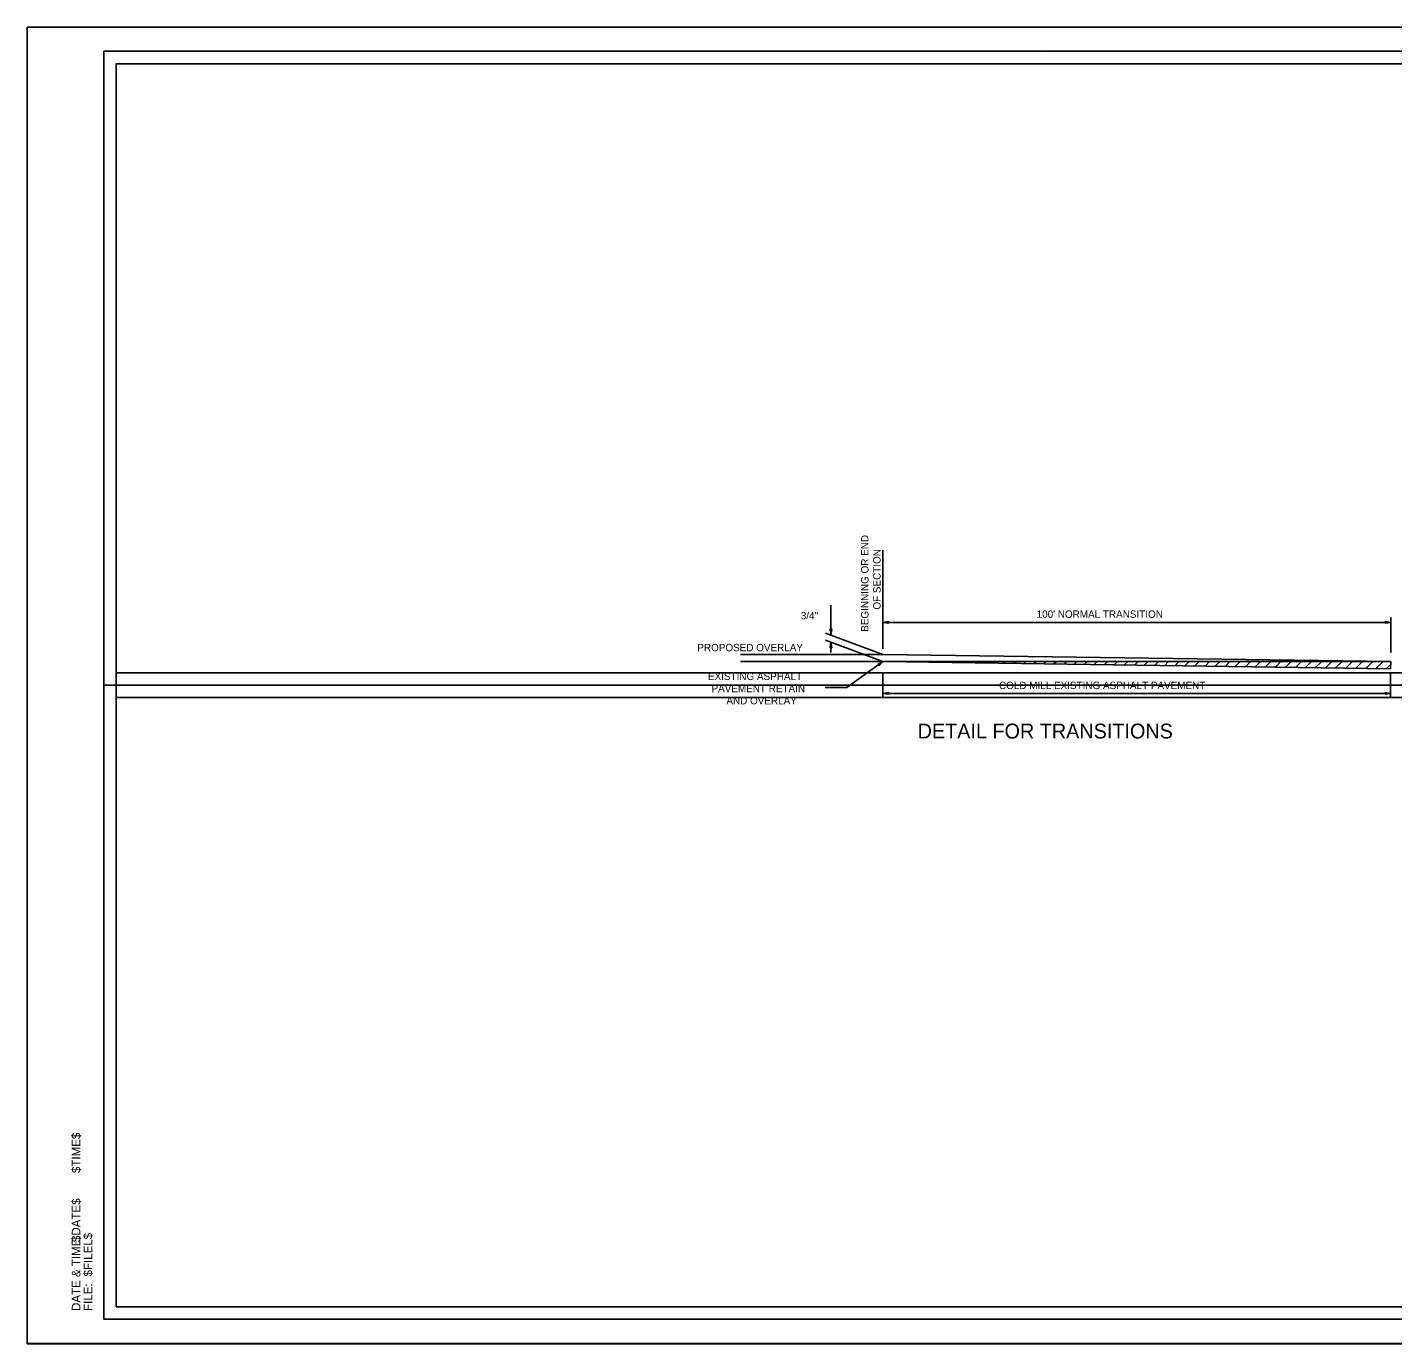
# Model space of a CAD drawing. Extents: x 1372039 to 1372773, y 376713 to 376926.
# Drawn here: x 1372039.3 to 1372260.6, y 376712.7 to 376926 of the extents above; entities that cross this region are included whole.
import ezdxf

# ---------------------------------------------------------------- set-up
doc = ezdxf.new("R2010")
doc.units = 0
for name, color, linetype in [('Default', 7, 'Continuous'), ('R_Border', 7, 'Continuous'), ('R_Border Plan-Plan', 7, 'Continuous'), ('R_No Plot', 7, 'Continuous')]:
    doc.layers.add(name, color=color, linetype=linetype)

msp = doc.modelspace()

# ---------------------------------------------------------------- linework, layer by layer
at = {"layer": 'Default'}
for p, q in [((1372177.98, 376825.29), (1372177.98, 376841.27)), ((1372169.54, 376827.56), (1372169.54, 376832.36)), ((1372260.29, 376824.67), (1372260.29, 376830.36)), ((1372169.41, 376828.45), (1372169.54, 376827.56)), ((1372169.41, 376828.45), (1372169.54, 376827.69)), ((1372169.68, 376828.45), (1372169.41, 376828.45)), ((1372169.46, 376828.45), (1372169.54, 376827.87)), ((1372169.46, 376828.45), (1372169.54, 376828)), ((1372169.5, 376828.45), (1372169.54, 376828.18)), ((1372169.5, 376828.45), (1372169.54, 376828.32)), ((1372169.68, 376828.45), (1372169.54, 376827.56)), ((1372169.59, 376828.45), (1372169.54, 376828.18)), ((1372169.63, 376828.45), (1372169.54, 376827.87)), ((1372169.63, 376828.45), (1372169.54, 376827.69)), ((1372169.59, 376828.45), (1372169.54, 376828)), ((1372169.54, 376828.45), (1372169.54, 376828.32)), ((1372178.92, 376829.69), (1372177.98, 376829.56)), ((1372177.98, 376829.56), (1372260.29, 376829.56)), ((1372178.92, 376829.43), (1372177.98, 376829.56)), ((1372178.92, 376829.65), (1372178.12, 376829.56)), ((1372178.92, 376829.43), (1372178.12, 376829.56)), ((1372178.92, 376829.65), (1372178.3, 376829.56)), ((1372178.92, 376829.47), (1372178.3, 376829.56)), ((1372178.92, 376829.6), (1372178.47, 376829.56)), ((1372178.92, 376829.47), (1372178.47, 376829.56)), ((1372178.92, 376829.6), (1372178.61, 376829.56)), ((1372178.92, 376829.52), (1372178.61, 376829.56)), ((1372178.92, 376829.56), (1372178.78, 376829.56)), ((1372178.92, 376829.52), (1372178.78, 376829.56)), ((1372178.92, 376829.43), (1372178.92, 376829.69)), ((1372259.36, 376829.69), (1372260.29, 376829.56)), ((1372259.36, 376829.69), (1372259.36, 376829.43)), ((1372259.36, 376829.65), (1372259.98, 376829.56)), ((1372259.36, 376829.65), (1372260.11, 376829.56)), ((1372259.36, 376829.6), (1372259.67, 376829.56)), ((1372259.36, 376829.6), (1372259.81, 376829.56)), ((1372259.36, 376829.43), (1372260.29, 376829.56)), ((1372259.36, 376829.52), (1372259.67, 376829.56)), ((1372259.36, 376829.47), (1372259.98, 376829.56)), ((1372259.36, 376829.43), (1372260.11, 376829.56)), ((1372259.36, 376829.47), (1372259.81, 376829.56)), ((1372259.36, 376829.52), (1372259.49, 376829.56)), ((1372259.36, 376829.56), (1372259.49, 376829.56)), ((1372177.98, 376824.36), (1372168.7, 376827.83)), ((1372177.98, 376823.21), (1372168.7, 376826.67)), ((1372169.41, 376825.43), (1372169.54, 376826.36)), ((1372169.41, 376825.43), (1372169.54, 376826.23)), ((1372169.46, 376825.43), (1372169.54, 376826.05)), ((1372169.46, 376825.43), (1372169.54, 376825.92)), ((1372169.68, 376825.43), (1372169.54, 376826.36)), ((1372169.54, 376824.67), (1372169.54, 376826.36)), ((1372169.63, 376825.43), (1372169.54, 376826.23)), ((1372169.63, 376825.43), (1372169.54, 376826.05)), ((1372169.59, 376825.43), (1372169.54, 376825.92)), ((1372154.89, 376824.36), (1372177.98, 376824.36)), ((1372169.41, 376825.43), (1372169.68, 376825.43)), ((1372169.5, 376825.43), (1372169.54, 376825.74)), ((1372169.5, 376825.43), (1372169.54, 376825.56)), ((1372169.59, 376825.43), (1372169.54, 376825.74)), ((1372169.54, 376825.43), (1372169.54, 376825.56)), ((1372260.29, 376823.21), (1372177.98, 376824.36)), ((1372154.89, 376823.21), (1372260.3, 376823.21)), ((1372172.12, 376818.99), (1372177.98, 376823.21)), ((1372177.14, 376822.76), (1372177.98, 376823.21)), ((1372177.14, 376822.76), (1372177.32, 376822.54)), ((1372177.19, 376822.76), (1372177.85, 376823.12)), ((1372177.19, 376822.76), (1372177.72, 376823.03)), ((1372177.19, 376822.72), (1372177.58, 376822.94)), ((1372177.19, 376822.72), (1372177.5, 376822.85)), ((1372177.23, 376822.68), (1372177.36, 376822.76)), ((1372177.23, 376822.68), (1372177.36, 376822.76)), ((1372177.27, 376822.59), (1372177.72, 376823.03)), ((1372177.27, 376822.63), (1372177.58, 376822.94)), ((1372177.27, 376822.63), (1372177.5, 376822.85)), ((1372177.32, 376822.54), (1372177.98, 376823.21)), ((1372177.32, 376822.59), (1372177.85, 376823.12)), ((1372260.25, 376822.05), (1372177.98, 376823.21)), ((1372177.98, 376817.48), (1372177.98, 376821.47)), ((1372181.22, 376823.16), (1372181.27, 376823.21)), ((1372182.85, 376823.14), (1372182.91, 376823.21)), ((1372184.47, 376823.12), (1372184.6, 376823.21)), ((1372186.13, 376823.1), (1372186.25, 376823.21)), ((1372187.75, 376823.07), (1372187.89, 376823.21)), ((1372189.38, 376823.05), (1372189.53, 376823.21)), ((1372191, 376823.03), (1372191.18, 376823.21)), ((1372192.66, 376823), (1372192.86, 376823.21)), ((1372194.28, 376822.98), (1372194.51, 376823.21)), ((1372195.94, 376822.96), (1372196.15, 376823.21)), ((1372197.52, 376822.93), (1372197.8, 376823.21)), ((1372199.19, 376822.91), (1372199.48, 376823.21)), ((1372200.81, 376822.89), (1372201.13, 376823.21)), ((1372202.47, 376822.86), (1372202.77, 376823.21)), ((1372204.05, 376822.84), (1372204.46, 376823.21)), ((1372205.71, 376822.82), (1372206.1, 376823.21)), ((1372207.34, 376822.8), (1372207.75, 376823.21)), ((1372208.96, 376822.77), (1372209.39, 376823.21)), ((1372210.58, 376822.75), (1372211.08, 376823.21)), ((1372212.24, 376822.73), (1372212.72, 376823.21)), ((1372213.86, 376822.7), (1372214.36, 376823.21)), ((1372215.48, 376822.68), (1372216.01, 376823.21)), ((1372217.1, 376822.66), (1372217.69, 376823.21)), ((1372218.77, 376822.64), (1372219.34, 376823.21)), ((1372220.34, 376822.61), (1372220.98, 376823.21)), ((1372222.01, 376822.59), (1372222.63, 376823.21)), ((1372223.67, 376822.57), (1372224.27, 376823.21)), ((1372225.29, 376822.54), (1372225.96, 376823.21)), ((1372226.91, 376822.52), (1372227.6, 376823.21)), ((1372228.54, 376822.5), (1372229.24, 376823.21)), ((1372230.2, 376822.48), (1372230.93, 376823.21)), ((1372231.82, 376822.45), (1372232.58, 376823.21)), ((1372233.44, 376822.43), (1372234.22, 376823.21)), ((1372235.06, 376822.41), (1372235.86, 376823.21)), ((1372236.73, 376822.38), (1372237.55, 376823.21)), ((1372238.3, 376822.36), (1372239.19, 376823.21)), ((1372239.97, 376822.34), (1372240.84, 376823.21)), ((1372241.59, 376822.31), (1372242.48, 376823.21)), ((1372243.25, 376822.29), (1372244.13, 376823.21)), ((1372244.83, 376822.27), (1372245.81, 376823.21)), ((1372246.49, 376822.25), (1372247.46, 376823.21)), ((1372248.12, 376822.23), (1372249.1, 376823.21)), ((1372249.74, 376822.2), (1372250.74, 376823.21)), ((1372251.36, 376822.18), (1372252.43, 376823.21)), ((1372253.02, 376822.15), (1372254.07, 376823.21)), ((1372254.64, 376822.13), (1372255.72, 376823.21)), ((1372256.26, 376822.11), (1372257.36, 376823.21)), ((1372257.88, 376822.09), (1372259.05, 376823.21)), ((1372259.55, 376822.06), (1372260.28, 376822.79)), ((1372260.29, 376823.21), (1372260.25, 376822.05)), ((1372260.25, 376817.48), (1372260.25, 376821.47)), ((1372168.61, 376818.99), (1372172.12, 376818.99)), ((1372178.88, 376818.19), (1372177.98, 376818.06)), ((1372178.88, 376818.19), (1372177.98, 376818.06)), ((1372260.25, 376818.06), (1372177.98, 376818.06)), ((1372178.88, 376817.92), (1372177.98, 376818.06)), ((1372178.88, 376817.92), (1372177.98, 376818.06)), ((1372178.88, 376818.19), (1372178.12, 376818.06)), ((1372178.88, 376818.19), (1372178.12, 376818.06)), ((1372178.88, 376817.97), (1372178.12, 376818.06)), ((1372178.88, 376817.97), (1372178.12, 376818.06)), ((1372178.88, 376818.15), (1372178.3, 376818.06)), ((1372178.88, 376818.15), (1372178.3, 376818.06)), ((1372178.88, 376817.97), (1372178.3, 376818.06)), ((1372178.88, 376817.97), (1372178.3, 376818.06)), ((1372178.88, 376818.15), (1372178.43, 376818.06)), ((1372178.88, 376818.15), (1372178.43, 376818.06)), ((1372178.88, 376818.01), (1372178.43, 376818.06)), ((1372178.88, 376818.01), (1372178.43, 376818.06)), ((1372178.88, 376818.1), (1372178.61, 376818.06)), ((1372178.88, 376818.1), (1372178.61, 376818.06)), ((1372178.88, 376818.01), (1372178.61, 376818.06)), ((1372178.88, 376818.01), (1372178.61, 376818.06)), ((1372178.88, 376818.1), (1372178.74, 376818.06)), ((1372178.88, 376818.1), (1372178.74, 376818.06)), ((1372178.88, 376818.06), (1372178.74, 376818.06)), ((1372178.88, 376818.06), (1372178.74, 376818.06)), ((1372178.88, 376817.92), (1372178.88, 376818.19)), ((1372178.88, 376817.92), (1372178.88, 376818.19)), ((1372259.36, 376818.19), (1372260.25, 376818.06)), ((1372259.36, 376818.19), (1372260.11, 376818.06)), ((1372259.36, 376818.19), (1372259.36, 376817.92)), ((1372259.36, 376818.15), (1372259.94, 376818.06)), ((1372259.36, 376818.15), (1372259.81, 376818.06)), ((1372259.36, 376818.1), (1372259.63, 376818.06)), ((1372259.36, 376818.1), (1372259.49, 376818.06)), ((1372259.36, 376817.92), (1372260.25, 376818.06)), ((1372259.36, 376818.01), (1372259.63, 376818.06)), ((1372259.36, 376817.97), (1372259.94, 376818.06)), ((1372259.36, 376817.97), (1372260.11, 376818.06)), ((1372259.36, 376818.01), (1372259.81, 376818.06)), ((1372259.36, 376818.06), (1372259.49, 376818.06))]:
    msp.add_line(p, q, dxfattribs=at)
at = {"layer": 'R_Border'}
for p, q in [((1372051.71, 376922.11), (1372367.89, 376922.11)), ((1372051.71, 376716.65), (1372051.71, 376922.11)), ((1372204.23, 376921.85), (1372204.23, 376921.85)), ((1372204.23, 376921.85), (1372204.23, 376921.85)), ((1372051.71, 376716.65), (1372051.71, 376716.65)), ((1372367.89, 376716.65), (1372051.71, 376716.65))]:
    msp.add_line(p, q, dxfattribs=at)
at = {"layer": 'R_Border Plan-Plan'}
msp.add_line((1372051.71, 376819.38), (1372367.89, 376819.38), dxfattribs=at)
at = {"layer": 'R_No Plot'}
for p, q in [((1372039.31, 376926), (1372372.64, 376926)), ((1372039.31, 376712.67), (1372372.64, 376712.67))]:
    msp.add_line(p, q, dxfattribs=at)
for points in [[(1372039.3, 376926), (1372372.64, 376926), (1372372.64, 376712.66), (1372039.3, 376712.66)], [(1372053.71, 376920.11), (1372303.25, 376920.11), (1372303.25, 376910.23), (1372320.79, 376910.23), (1372344.89, 376910.23), (1372344.89, 376887.89), (1372365.89, 376887.89), (1372365.89, 376718.65), (1372053.71, 376718.65)], [(1372365.89, 376821.38), (1372053.71, 376821.38), (1372053.71, 376920.11), (1372303.25, 376920.11), (1372303.25, 376910.23), (1372320.79, 376910.23), (1372344.89, 376910.23), (1372344.89, 376887.89), (1372365.89, 376887.89)], [(1372053.71, 376817.38), (1372365.89, 376817.38), (1372365.89, 376718.65), (1372053.71, 376718.65)]]:
    msp.add_lwpolyline(points, close=True, dxfattribs=at)

# ---------------------------------------------------------------- texts
at = {"layer": 'Default'}
for s, height, p in [('BEGINNING OR END', 1.2, (1372175.64, 376828.04)), ('OF SECTION', 1.2, (1372177.61, 376831.63)), ('$TIME$', 1.397, (1372047.91, 376740.32)), ('$DATE$', 1.397, (1372047.91, 376729.14)), ('DATE & TIME:', 1.3968, (1372047.91, 376717.97)), ('$FILEL$', 1.397, (1372049.83, 376723.56)), ('FILE: ', 1.397, (1372049.83, 376717.97))]:
    msp.add_text(s, height=height, rotation=90, dxfattribs=at).set_placement(p)
for s, height, p in [('3/4"', 1.2, (1372164.67, 376830.06)), ("100' NORMAL TRANSITION", 1.2, (1372202.9, 376830.3)), ('PROPOSED OVERLAY', 1.2, (1372147.9, 376824.88)), ('EXISTING ASPHALT', 1.2, (1372149.63, 376820.22)), ('PAVEMENT RETAIN', 1.2, (1372150.2, 376818.25)), ('COLD MILL EXISTING ASPHALT PAVEMENT', 1.2, (1372196.8, 376818.75)), ('AND OVERLAY', 1.2, (1372152.61, 376816.28)), ('DETAIL FOR TRANSITIONS', 2.4, (1372183.61, 376810.75))]:
    msp.add_text(s, height=height, dxfattribs=at).set_placement(p)

doc.saveas('drawing.dxf')
